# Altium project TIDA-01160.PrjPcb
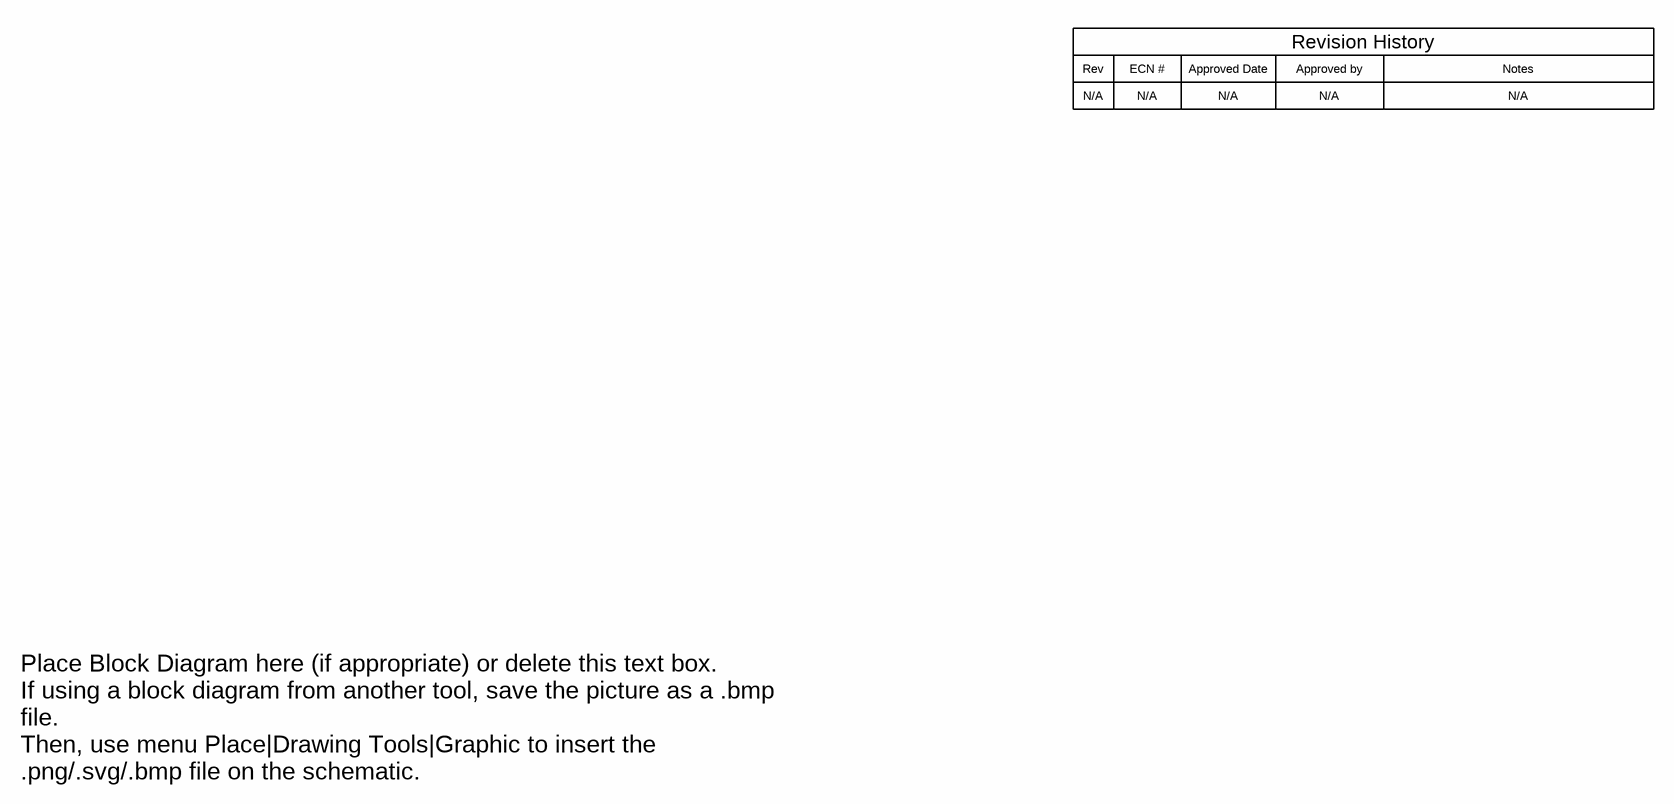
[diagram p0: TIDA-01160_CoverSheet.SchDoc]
CopyrightYear: 2016; EVM_Orderable: N/A; PCB_Layout: Akshay Labhe; PCB_Rev: E1; PRJ_Customer: Public Release; PRJ_Engineer: Yamini Sharma; PRJ_Number: TIDA-01160; PRJ_Title: Isolated Gate Driver for IGBT/SiC; SCH_Rev: E1; TechSupport: http://www.ti.com/support; TID: TIDA-01160
3 sheets, 53 parts. Net scope: global (net labels, ports and power ports of the same name join across sheets).
Board file: TIDA-01160.PcbDoc
Sheets:
  TIDA-01160_CoverSheet.SchDoc
  TIDA-01160_Sheet1.SchDoc
  TIDA-01160_Hardware.SchDoc

## Sheet TIDA-01160_CoverSheet.SchDoc
size 431 x 279 mm; Date: Not shown in title block; ApprovedBy: Not shown in title block; CheckedBy: Not shown in title block; Author: Not shown in title block; CompanyName: Not shown in title block; DrawnBy: Yamini Sharma; Engineer: Not shown in title block; Organization: Not shown in title block; Address1: Not shown in title block; Address2: Not shown in title block; Address3: Not shown in title block; Address4: Not shown in title block; DocumentNumber: 1; Revision: Use project parameter SCH_Rev; SheetNumber: 1; SheetTotal: 3; PageSetup: Record=PageOptions¦CenterHorizontal=True¦CenterVertical=True¦PrintScale=1.00¦XCorrection=1.00¦YCorrection=1.00¦PrintKind=0¦BorderSize=5000000¦LeftOffset=0¦BottomOffset=0¦Orientation=2¦PaperLength=1000¦PaperWidth=1000¦Scale=100¦PaperSource=15¦PrintQuality=600¦MediaType=1¦DitherType=10¦PaperKind=Letter¦PrintScaleMode=1

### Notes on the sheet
- Rev
- N/A
- ECN #
- Approved Date
- Approved by
- Revision History
- Notes
- Place Block Diagram here (if appropriate) or delete this text box.
  If using a block diagram from another tool, save the picture as a .bmp file.
  Then, use menu Place|Drawing Tools|Graphic to insert the .png/.svg/.bmp file on the schematic.

## Sheet TIDA-01160_Sheet1.SchDoc
size 431 x 279 mm; Date: Not shown in title block; ApprovedBy: Not shown in title block; CheckedBy: Not shown in title block; Author: Not shown in title block; CompanyName: Not shown in title block; DrawnBy: Yamini Sharma; Engineer: Not shown in title block; Organization: Not shown in title block; Address1: Not shown in title block; Address2: Not shown in title block; Address3: Not shown in title block; Address4: Not shown in title block; DocumentNumber: 1; Revision: Use project parameter SCH_Rev; SheetNumber: 2; SheetTotal: 3; PageSetup: Record=PageOptions¦CenterHorizontal=True¦CenterVertical=True¦PrintScale=1.00¦XCorrection=1.00¦YCorrection=1.00¦PrintKind=0¦BorderSize=5000000¦LeftOffset=0¦BottomOffset=0¦Orientation=2¦PaperLength=1000¦PaperWidth=1000¦Scale=100¦PaperSource=15¦PrintQuality=600¦MediaType=1¦DitherType=10¦PaperKind=Letter¦PrintScaleMode=1
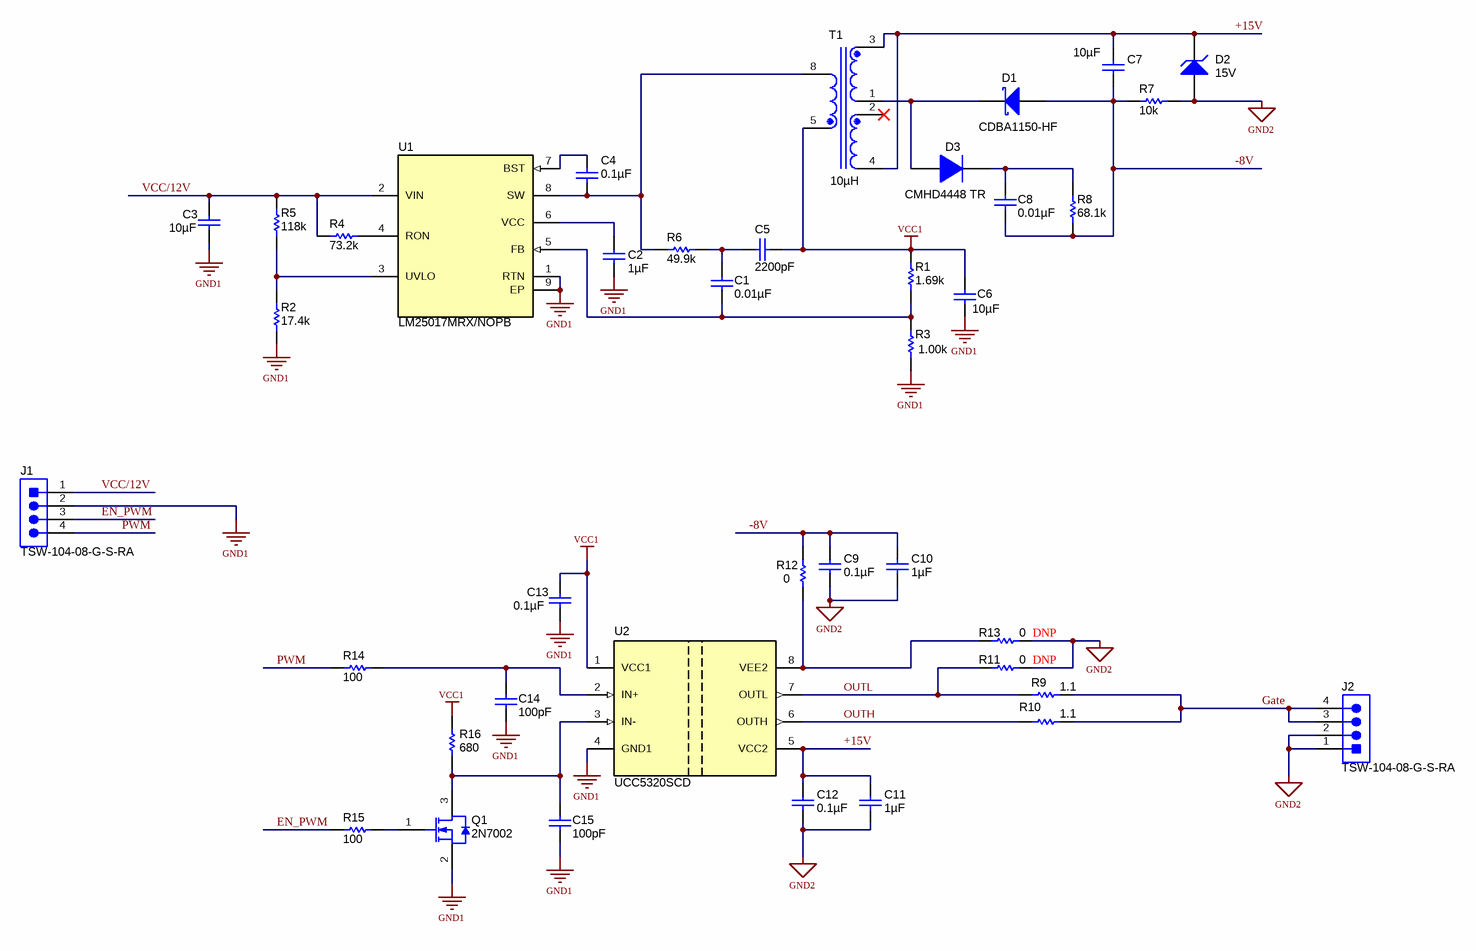
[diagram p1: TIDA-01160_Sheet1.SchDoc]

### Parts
C1  ValueDisplayed: 0.01µF  [0603]  (hidden comment: C0603C103J5RACTU)
C2  ValueDisplayed: 1µF  [0603]  (hidden comment: C0603C105K3RACTU)
C3  ValueDisplayed: 10µF  [1210_280]  (hidden comment: C3225X7R1E106M250AC)
C4  ValueDisplayed: 0.1µF  [0603]  (hidden comment: 06035C104KAT2A)
C5  ValueDisplayed: 2200pF  [0603]  (hidden comment: C0603C222K5RACTU)
C6  ValueDisplayed: 10µF  [1210_280]  (hidden comment: C3225X7R1E106M250AC)
C7  ValueDisplayed: 10µF  [1210_280]  (hidden comment: C3225X7R1H106M250AC)
C8  ValueDisplayed: 0.01µF  [0805_HV]  (hidden comment: GRM21BR72E103KW03L)
C9  ValueDisplayed: 0.1µF  [0603]  (hidden comment: 06035C104KAT2A)
C10  ValueDisplayed: 1µF  [0603]  (hidden comment: C1608X5R1H105K080AB)
C11  ValueDisplayed: 1µF  [0603]  (hidden comment: C1608X5R1H105K080AB)
C12  ValueDisplayed: 0.1µF  [0603]  (hidden comment: 06035C104KAT2A)
C13  ValueDisplayed: 0.1µF  [0603]  (hidden comment: 06035C104KAT2A)
C14  ValueDisplayed: 100pF  [0603]  (hidden comment: 06035A101JAT2A)
C15  ValueDisplayed: 100pF  [0603]  (hidden comment: 06035A101JAT2A)
D1  CDBA1150-HF  [SMA]
D2  value 15V  [SOD-123]  (hidden comment: BZT52C15-7-F)
D3  CMHD4448 TR  [SOD-123]
J1  TSW-104-08-G-S-RA  [TSW-104-08-G-S-RA]
J2  TSW-104-08-G-S-RA  [TSW-104-08-G-S-RA]
Q1  2N7002  [SOT-23]
R1  ValueDisplayed: 1.69k  [0603]  (hidden comment: RC0603FR-071K69L)
R2  ValueDisplayed: 17.4k  [0603]  (hidden comment: CRCW060317K4FKEA)
R3  ValueDisplayed: 1.00k  [0603]  (hidden comment: RC0603FR-071KL)
R4  ValueDisplayed: 73.2k  [0603]  (hidden comment: CRCW060373K2FKEA)
R5  ValueDisplayed: 118k  [0603]  (hidden comment: CRCW0603118KFKEA)
R6  ValueDisplayed: 49.9k  [0603]  (hidden comment: CRCW060349K9FKEA)
R7  ValueDisplayed: 10k  [0603]  (hidden comment: RC0603JR-0710KL)
R8  ValueDisplayed: 68.1k  [1206]  (hidden comment: CRCW120668K1FKEA)
R9  ValueDisplayed: 1.1  [2010]  (hidden comment: CRCW20101R10JNEF)
R10  ValueDisplayed: 1.1  [2010]  (hidden comment: CRCW20101R10JNEF)
R11  ValueDisplayed: 0  Installation: DNP  [0603]  (hidden comment: CRCW06030000Z0EA)
R12  ValueDisplayed: 0  [0603]  (hidden comment: CRCW06030000Z0EA)
R13  ValueDisplayed: 0  Installation: DNP  [0603]  (hidden comment: CRCW06030000Z0EA)
R14  ValueDisplayed: 100  [0603]  (hidden comment: CRCW0603100RJNEA)
R15  ValueDisplayed: 100  [0603]  (hidden comment: CRCW0603100RJNEA)
R16  ValueDisplayed: 680  [0603]  (hidden comment: RC0603FR-07680RL)
T1  ValueDisplayed: 10µH  [WURTH_750315248]  (hidden comment: 750343468Rev02)
U1  LM25017MRX/NOPB  [DDA0008B_N]
U2  UCC5320SCD  [D0008B_HV]

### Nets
GND1: C2.2 C3.2 C6.1 C13.2 C14.1 C15.1 J1.2 Q1.2(S) R2.1 R3.1 U1.1(RTN) U1.9(EP) U2.4(GND1)
GND2: C9.2 C10.2 C11.2 C12.2 D2.2(A) J2.1 J2.2 R7.1 R11.2 R13.2
VCC1: C5.1 C6.2 C13.1 R1.2 R16.2 T1.5 U2.1(VCC1)
+15V: C7.1 C11.1 C12.1 D2.1(K) T1.3 T1.4 U2.5(VCC2)
-8V: C7.2 C8.2 C9.1 C10.1 D1.2(A) R7.2 R8.1 R12.1
EN_PWM: J1.3 R15.2
Gate: J2.3 J2.4 R9.2 R10.2
OUTH: R10.1 U2.6(OUTH)
OUTL: R9.1 R11.1 U2.7(OUTL)
PWM: J1.4 R14.2
VCC/12V: C3.1 J1.1 R4.1 R5.2 U1.2(VIN)
NetC1_1: C1.1 C5.2 R6.2
NetC1_2: C1.2 R1.1 R3.2 U1.5(FB)
NetC2_1: C2.1 U1.6(VCC)
NetC4_1: C4.1 U1.7(BST)
NetC4_2: C4.2 R6.1 T1.8 U1.8(SW)
NetC8_1: C8.1 D3.1(K) R8.2
NetC14_2: C14.2 R14.1 U2.2(IN+)
NetC15_2: C15.2 Q1.3(D) R16.1 U2.3(IN-)
NetD1_1: D1.1(K) D3.2(A) T1.1
NetQ1_1: Q1.1(G) R15.1
NetR2_2: R2.2 R5.1 U1.3(UVLO)
NetR4_2: R4.2 U1.4(RON)
NetR12_2: R12.2 R13.1 U2.8(VEE2)

Not connected (* = marked no-connect by the designer): T1 2*

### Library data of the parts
C1 = C0603C103J5RACTU: CAP, CERM, 0.01 µF, 50 V, +/- 5%, X7R, 0603; Manufacturer: Kemet; Polarized: N; CompType: Capacitor; Value: 0.01uF; U/M: EA; Cap_F: 0.00000001; Tolerance_%: 5; Value1: Unknown; VDC_V: 50; Value2: 50V; TaMin_C: -55; TaMax_C: 125; SizeArea_mm2: 1.28; SizeAreaWB_mm2: 4.68; SizeX_mm: 1.6; SizeY_mm: 0.8; SizeZ_mm: 1; AEC Category: Q200
C2 = C0603C105K3RACTU: CAP, CERM, 1 µF, 25 V, +/- 10%, X7R, 0603; Manufacturer: Kemet; Polarized: N; CompType: Capacitor; Value: 1uF; U/M: EA; Cap_F: 0.000001; Tolerance_%: 10; Value1: Unknown; VDC_V: 25; Value2: 25V; TaMin_C: -55; TaMax_C: 125; SizeArea_mm2: 1.28; SizeAreaWB_mm2: 4.68; SizeX_mm: 1.6; SizeY_mm: 0.8; SizeZ_mm: 1; AEC Category: Q200
C3 C6 = C3225X7R1E106M250AC: CAP, CERM, 10 µF, 25 V, +/- 20%, X7R, 1210; Manufacturer: TDK; Polarized: N; CompType: Capacitor; Value: 10uF; U/M: EA; Cap_F: 0.00001; Tolerance_%: 20; Value1: Unknown; VDC_V: 25; Value2: 25V; TaMin_C: -55; TaMax_C: 125; Cap_Case: 1210; SizeArea_mm2: 8; SizeAreaWB_mm2: 14.7; SizeX_mm: 3.2; SizeY_mm: 2.5; SizeZ_mm: 2.8; AEC Category: Q200
C4 C9 C12 C13 = 06035C104KAT2A: CAP, CERM, 0.1 µF, 50 V, +/- 10%, X7R, 0603; Manufacturer: AVX; Polarized: N; CompType: Capacitor; Value: 0.1uF; U/M: EA; Cap_F: 0.0000001; Tolerance_%: 10; Value1: Unknown; VDC_V: 50; Value2: 50V; TaMin_C: -55; TaMax_C: 125; SizeArea_mm2: 1.28; SizeAreaWB_mm2: 4.68; SizeX_mm: 1.6; SizeY_mm: 0.8; SizeZ_mm: 1; AEC Category: Q200
C5 = C0603C222K5RACTU: CAP, CERM, 2200 pF, 50 V, +/- 10%, X7R, 0603; Manufacturer: Kemet; Polarized: N; CompType: Capacitor; Value: 2200pF; U/M: EA; Cap_F: 0.0000000022; Tolerance_%: 10; Value1: Unknown; VDC_V: 50; Value2: 50V; TaMin_C: -55; TaMax_C: 125; SizeArea_mm2: 1.28; SizeAreaWB_mm2: 4.68; SizeX_mm: 1.6; SizeY_mm: 0.8; SizeZ_mm: 1; AEC Category: Q200
C7 = C3225X7R1H106M250AC: CAP, CERM, 10 µF, 50 V, +/- 20%, X7R, 1210; Manufacturer: TDK; Polarized: N; CompType: Capacitor; Value: 10uF; U/M: EA; Cap_F: 0.00001; Tolerance_%: 20; Value1: Unknown; VDC_V: 50; Value2: 50V; TaMin_C: -55; TaMax_C: 125; Cap_Case: 1210; SizeArea_mm2: 8; SizeAreaWB_mm2: 14.7; SizeX_mm: 3.2; SizeY_mm: 2.5; SizeZ_mm: 2.8; AEC Category: Q200
C8 = GRM21BR72E103KW03L: CAP, CERM, 0.01 µF, 250 V, +/- 10%, X7R, 0805; Manufacturer: MuRata; Polarized: N; CompType: Capacitor; Value: 0.01uF; U/M: EA; Cap_F: 0.00000001; Tolerance_%: 10; Value1: Unknown; VDC_V: 250; Value2: 250V; TaMin_C: -55; TaMax_C: 125; Cap_Case: 0805; SizeArea_mm2: 2.5; SizeAreaWB_mm2: 6.75; SizeX_mm: 2; SizeY_mm: 1.25; SizeZ_mm: 1.45; AEC Category: Q200
C10 C11 = C1608X5R1H105K080AB: CAP, CERM, 1 µF, 50 V, +/- 10%, X5R, 0603; Manufacturer: TDK; Polarized: N; CompType: Capacitor; Value: 1uF; U/M: EA; Cap_F: 0.000001; Tolerance_%: 10; ESR_ohm: 0.005522; Value1: 0.005522 ohm; VDC_V: 50; Value2: 50V; IRMS_A: 2.21617; TaMin_C: -55; TaMax_C: 85; SizeArea_mm2: 1.28; SizeAreaWB_mm2: 4.68; SizeX_mm: 1.6; SizeY_mm: 0.8; SizeZ_mm: 1; AEC Category: Q200
C14 C15 = 06035A101JAT2A: CAP, CERM, 100 pF, 50 V, +/- 5%, C0G/NP0, 0603; Manufacturer: AVX; Polarized: N; CompType: Capacitor; Value: 100pF; U/M: EA; Cap_F: 0.0000000001; Tolerance_%: 5; ESR_ohm: 0.119; Value1: 0.119 ohm; VDC_V: 50; Value2: 50V; TaMin_C: -55; TaMax_C: 125; SizeArea_mm2: 1.28; SizeAreaWB_mm2: 4.68; SizeX_mm: 1.6; SizeY_mm: 0.8; SizeZ_mm: 1; AEC Category: Q200
D1 = STPS1150A: Diode, Schottky, 150 V, 1 A, Surface Mount DO-214AC, SMA; Manufacturer: Comchip Technology; U/M: EA; Vf_V: 0.78; Value: 150V; Value1: 1A; Value2: 0.78V; Io_A: 1; Vr_V: 150; TJmax_C: 175; RJC_CperW: 30; SizeAreaWB_mm2: 37.3428; SizeArea_mm2: 16.3228; SizeX_mm: 5.59; SizeY_mm: 2.92; SizeZ_mm: 2.87; AEC Category: Q101; AEC Qualified: N
D2 = BZT52C15-7-F: Diode, Zener, 15 V, 370 mW, AEC-Q101, SOD-123; Manufacturer: Diodes Inc.; SymbolCreator: a0412235; U/M: EA; Power_W: 0.37; Vz_V: 15; Value1: 0.37W; RJA_CperW: 338; AEC Category: Q101; AEC Qualified: Y
D3 = CMHD4448 TR: Diode, Switching, 100 V, 0.25 A, SOD-123; Manufacturer: Central Semiconductor; U/M: EA; Vf_V: 1; Value: 100V; Value1: 0.25A; Value2: 1V; Io_A: 0.25; Vr_V: 100; TJmax_C: 150; SizeAreaWB_mm2: 13.095; SizeArea_mm2: 6.545; SizeX_mm: 3.85; SizeY_mm: 1.7; SizeZ_mm: 1.35; AEC Category: Q101
J1 J2 = TSW-104-08-G-S-RA: Header, 100mil, 4x1, Gold, R/A, TH; Manufacturer: Samtec; SymbolCreator: a0412235; Pitch_mm: 2.54; Gender: Male; Shrouded: N; Row_Count: 1; Current_A: 6.3; Voltage_V: 550; Cert_CSA: Y
Q1 = 2N7002: MOSFET, N-CH, 60 V, 115 A, SOT-23; Manufacturer: Fairchild Semiconductor; Alternate Manufacturer: None; U/M: EA; ChType: N; Value: 60V; VdsMax_V: 60; Value1: ? ohm; Value2: ? nC; Vgs_V: 20; IdsMax_A: 115; SizeAreaWB_mm2: 14; SizeArea_mm2: 7.5; SizeX_mm: 2.5; SizeY_mm: 3; SizeZ_mm: 1.1; AEC Category: Q101
R1 = RC0603FR-071K69L: RES, 1.69 k, 1%, 0.1 W, 0603; Manufacturer: Yageo America; CompType: Resistor; Value: 1.69k; Res_ohm: 1690; Value_Code: 1k69; Tolerance_%: 1; Power_W: 0.1; Value2: 0.1W; VDC_V: 150; TempCo: 200 ppm/C; SizeArea_mm2: 1.28; SizeX_mm: 1.6; SizeY_mm: 0.8; EIA_Code: E96; U/M: EA; AEC Category: Q200
R2 = CRCW060317K4FKEA: RES, 17.4 k, 1%, 0.1 W, 0603; Manufacturer: Vishay-Dale; CompType: Resistor; Value: 17.4k; Res_ohm: 17400; Value_Code: 17k4; Tolerance_%: 1; Power_W: 0.1; Value2: 0.1W; VDC_V: 75; TempCo: 100 ppm/C; SizeArea_mm2: 1.28; SizeX_mm: 1.6; SizeY_mm: 0.8; EIA_Code: E96; U/M: EA; AEC Category: Q200
R3 = RC0603FR-071KL: RES, 1.00 k, 1%, 0.1 W, 0603; Manufacturer: Yageo America; CompType: Resistor; Value: 1.00k; Res_ohm: 1000; Value_Code: 1k00; Tolerance_%: 1; Power_W: 0.1; Value2: 0.1W; VDC_V: 150; TempCo: 200 ppm/C; SizeArea_mm2: 1.28; SizeX_mm: 1.6; SizeY_mm: 0.8; EIA_Code: E96; U/M: EA; AEC Category: Q200
R4 = CRCW060373K2FKEA: RES, 73.2 k, 1%, 0.1 W, 0603; Manufacturer: Vishay-Dale; CompType: Resistor; Value: 73.2k; Res_ohm: 73200; Value_Code: 73k2; Tolerance_%: 1; Power_W: 0.1; Value2: 0.1W; VDC_V: 75; TempCo: 100 ppm/C; SizeArea_mm2: 1.28; SizeX_mm: 1.6; SizeY_mm: 0.8; EIA_Code: E96; U/M: EA; AEC Category: Q200
R5 = CRCW0603118KFKEA: RES, 118 k, 1%, 0.1 W, 0603; Manufacturer: Vishay-Dale; CompType: Resistor; Value: 118k; Res_ohm: 118000; Tolerance_%: 1; Power_W: 0.1; Value2: 0.1W; VDC_V: 75; TempCo: 100 ppm/C; SizeArea_mm2: 1.28; SizeX_mm: 1.6; SizeY_mm: 0.8; EIA_Code: E96; U/M: EA; AEC Category: Q200
R6 = CRCW060349K9FKEA: RES, 49.9 k, 1%, 0.1 W, 0603; Manufacturer: Vishay-Dale; CompType: Resistor; Value: 49.9k; Res_ohm: 49900; Value_Code: 49k9; Tolerance_%: 1; Power_W: 0.1; Value2: 0.1W; VDC_V: 75; TempCo: 100 ppm/C; SizeArea_mm2: 1.28; SizeX_mm: 1.6; SizeY_mm: 0.8; EIA_Code: E96; U/M: EA; AEC Category: Q200
R7 = RC0603JR-0710KL: RES, 10 k, 5%, 0.1 W, 0603; Manufacturer: Yageo America; CompType: Resistor; Value: 10k; Res_ohm: 10000; Value_Code: 10k0; Tolerance_%: 5; Power_W: 0.1; Value2: 0.1W; VDC_V: 50; TempCo: 100 ppm/C; SizeArea_mm2: 1.28; SizeX_mm: 1.6; SizeY_mm: 0.8; SizeZ_mm: 1; EIA_Code: E24; U/M: EA; AEC Category: Q200
R8 = CRCW120668K1FKEA: RES, 68.1 k, 1%, 0.25 W, 1206; Manufacturer: Vishay-Dale; CompType: Resistor; Value: 68.1k; Res_ohm: 68100; Value_Code: 68k1; Tolerance_%: 1; Power_W: 0.25; Value2: 0.25W; VDC_V: 200; TempCo: 100 ppm/C; SizeArea_mm2: 5.12; SizeX_mm: 3.2; SizeY_mm: 1.6; SizeZ_mm: 1.35; EIA_Code: E96; U/M: EA; AEC Category: Q200
R9 R10 = CRCW20101R10JNEF: RES, 1.1, 5%, 0.75 W, AEC-Q200 Grade 0, 2010; Manufacturer: Vishay-Dale; CompType: Resistor; Value: 1.1; Value_Code: 1R10; Tolerance_%: 5; Power_W: 0.75; Value2: 0.75W; VDC_V: 400; TempCo: 200 ppm/C; SizeArea_mm2: 12.5; SizeY_mm: 2.5; SizeZ_mm: 1.66; EIA_Code: E24; U/M: EA; AEC Category: Q200; AEC Qualified: Y; AEC Grade: 0
R11-R13 = CRCW06030000Z0EA: RES, 0, 5%, 0.1 W, 0603; Manufacturer: Vishay-Dale; CompType: Resistor; Value: 0; Value_Code: 0000; Tolerance_%: 5; Power_W: 0.1; Value2: 0.1W; VDC_V: 75; TempCo: 200 ppm/C; EIA_Code: E24; U/M: EA; AEC Category: Q200
R14 R15 = CRCW0603100RJNEA: RES, 100, 5%, 0.1 W, 0603; Manufacturer: Vishay-Dale; CompType: Resistor; Value: 100; Value_Code: 100R; Tolerance_%: 5; Power_W: 0.1; Value2: 0.1W; VDC_V: 75; TempCo: 200 ppm/C; SizeArea_mm2: 1.28; SizeX_mm: 1.6; SizeY_mm: 0.8; SizeZ_mm: 1; EIA_Code: E24; U/M: EA; AEC Category: Q200
R16 = RC0603FR-07680RL: RES, 680, 1%, 0.1 W, 0603; Manufacturer: Yageo America; CompType: Resistor; Value: 680; Value_Code: 680R; Tolerance_%: 1; Power_W: 0.1; Value2: 0.1W; VDC_V: 150; TempCo: 200 ppm/C; SizeArea_mm2: 1.28; SizeX_mm: 1.6; SizeY_mm: 0.8; U/M: EA; AEC Category: Q200
T1 = 760390015: Transformer, 10µH, SMT; Manufacturer: Wurth Elektronik; SymbolCreator: Altium; Lp: 475; DCR_ohm: 0.35; Ns1toNp: 2; Rs1: 0.57
U1 = LM25017MRX/NOPB: 48V, 650mA Constant On-Time Synchronous Buck Regulator, DDA0008B; Alternate PartNumber: LM25017MR/NOPB; Manufacturer: Texas Instruments; SymbolCreator: a0412235; SizeArea_mm2: 31; SizeAreaWB_mm2: 57.4; SizeX_mm: 5; SizeY_mm: 6.2; SizeZ_mm: 1.7; CompType: IC; U/M: EA
U2 = UCC5320SCD: Isolated Gate Drivers with High CMTI and Scalable Drive Strength, D0008B (SOIC-8); Manufacturer: Texas Instruments; SymbolCreator: a0411947; SizeArea_mm2: 29.4; SizeAreaWB_mm2: 55.2; SizeX_mm: 6; SizeY_mm: 4.9; SizeZ_mm: 1.75; CompType: IC; U/M: EA

## Sheet TIDA-01160_Hardware.SchDoc
size 431 x 279 mm; Date: Not shown in title block; ApprovedBy: Not shown in title block; CheckedBy: Not shown in title block; Author: Not shown in title block; CompanyName: Not shown in title block; DrawnBy: Yamini Sharma; Engineer: Not shown in title block; Organization: Not shown in title block; Address1: Not shown in title block; Address2: Not shown in title block; Address3: Not shown in title block; Address4: Not shown in title block; DocumentNumber: 1; Revision: Use project parameter SCH_Rev; SheetNumber: 3; SheetTotal: 3; PageSetup: Record=PageOptions¦CenterHorizontal=True¦CenterVertical=True¦PrintScale=1.00¦XCorrection=1.00¦YCorrection=1.00¦PrintKind=0¦BorderSize=5000000¦LeftOffset=0¦BottomOffset=0¦Orientation=2¦PaperLength=1000¦PaperWidth=1000¦Scale=100¦PaperSource=15¦PrintQuality=600¦MediaType=1¦DitherType=10¦PaperKind=Letter¦PrintScaleMode=1
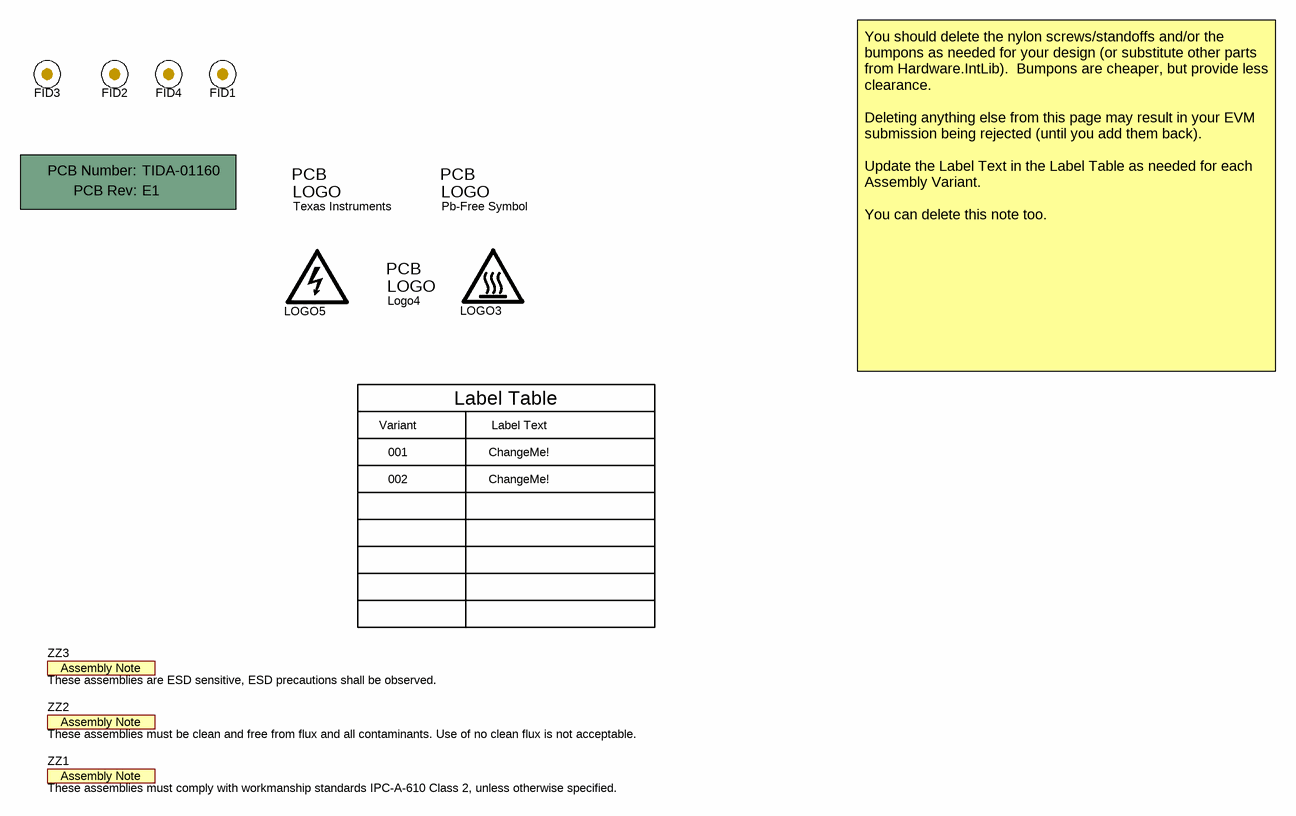
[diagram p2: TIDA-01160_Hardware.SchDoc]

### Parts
!PCB1  Printed Circuit Board  (value not drawn)  (mechanical)
FID1  Fiducial  [Fiducial10-20]  (value not drawn)
FID2  Fiducial  [Fiducial10-20]  (value not drawn)
FID3  Fiducial  [Fiducial10-20]  (value not drawn)
FID4  Fiducial  [Fiducial10-20]  (value not drawn)
Logo1  Texas Instruments  [TI_Symbol_Overlay_Small]  (no BOM)
Logo2  Pb-Free Symbol  [Pb-Free_Overlay_Small]  (no BOM)
LOGO3  CAUTION HOT SURFACE  [IEC_HotSurface_Small]  (value not drawn)  (no BOM)
Logo4  ESD Susceptible  [ESD_Overlay_Small]  (value not drawn)  (no BOM)
LOGO5  DANGER HIGH VOLTAGE  [IEC_HighVoltage_Small]  (value not drawn)  (no BOM)
ZZ1  These assemblies must comply with workmanship standards IPC-A-610 Class 2, unless otherwise specified.  [AssemblyNote]  (no BOM)
ZZ2  These assemblies must be clean and free from flux and all contaminants. Use of no clean flux is not acceptable.  [AssemblyNote]  (no BOM)
ZZ3  These assemblies are ESD sensitive, ESD precautions shall be observed.  [AssemblyNote]  (no BOM)

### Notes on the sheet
- Variant
- Label Table
- Label Text
- You should delete the nylon screws/standoffs and/or the bumpons as needed for your design (or substitute other parts from Hardware.IntLib).  Bumpons are cheaper, but provide less clearance.
  Deleting anything else from this page may result in your EVM submission being rejected (until you add them back).
  Update the Label Text in the Label Table as needed for each Assembly Variant.
  You can delete this note too.
- 001
- 002
- ChangeMe!

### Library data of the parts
!PCB1 = PCB: Manufacturer: Any; PartNumber: TIDA-01160; SymbolCreator: a0412235
FID1-FID4 = Fiducial: Fiducial mark.  There is nothing to buy or mount.; SymbolCreator: codlsc
Logo1 = TI_Logo: Texas Instrument Corporate Signature; SymbolCreator: codlsc
Logo2 = Pb-Free: SymbolCreator: a0412235
LOGO3 = IEC_HotSurface: IEC 61010-1 Hot Surface Warning; SymbolCreator: a0412235
Logo4 = ESD_Susceptible: ESD Susceptible Symbol; SymbolCreator: a0412235
LOGO5 = IEC_HighVoltage: IEC 61010-1 High Voltage Warning; SymbolCreator: a0412235
ZZ1-ZZ3 = AssemblyNote: SymbolCreator: codlsc

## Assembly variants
001: not fitted FID1 FID2 FID3 FID4 R11 R13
